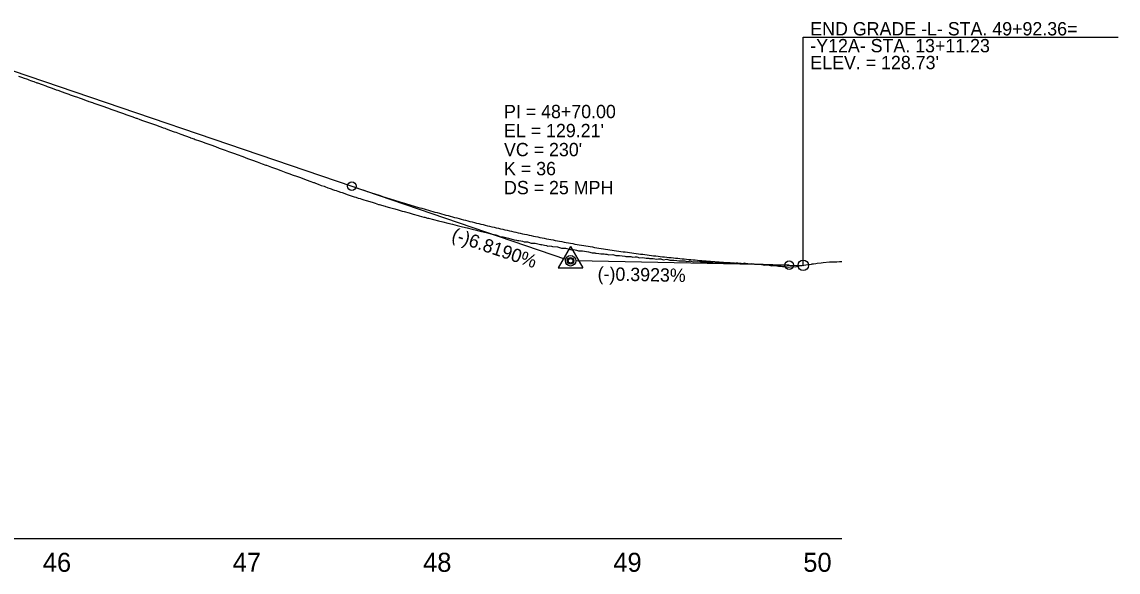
# Model space of a CAD drawing. Extents: x 1778432 to 1784301, y 601022 to 621789.
# Drawn here: x 1783724 to 1784301, y 621022 to 621311 of the extents above; entities that cross this region are included whole.
import ezdxf

# ---------------------------------------------------------------- set-up
doc = ezdxf.new("R2010")
doc.units = 0
for name, color, linetype in [('Exist Profile Cell', 7, 'Continuous'), ('Exist Vertical Profile Ground Line', 7, 'Continuous'), ('Exist Vertical Profile Horizontal Axis Label Major', 7, 'Continuous'), ('Prop PFL VPI Symbol CELL', 7, 'Continuous'), ('Prop Vertical Profile Curve Label', 7, 'Continuous'), ('Prop Vertical Profile Grade', 7, 'Continuous'), ('Prop Vertical Profile Grade Label', 7, 'Continuous'), ('Prop VPI Label', 7, 'Continuous')]:
    doc.layers.add(name, color=color, linetype=linetype)

msp = doc.modelspace()

# ---------------------------------------------------------------- linework, layer by layer
at = {"layer": 'Exist Profile Cell'}
msp.add_line((1780142.96, 621039.19), (1784155.69, 621039.19), dxfattribs=at)
at = {"layer": 'Exist Vertical Profile Ground Line'}
msp.add_lwpolyline([(1783722.62, 621282.4), (1783724.74, 621281.62), (1783725.14, 621281.48), (1783727.34, 621280.7), (1783728.1, 621280.43), (1783728.98, 621280.11), (1783729.99, 621279.74), (1783730.69, 621279.49), (1783732.29, 621278.9), (1783732.6, 621278.78), (1783735.09, 621277.91), (1783737.03, 621277.21), (1783737.73, 621276.96), (1783739.82, 621276.22), (1783741.14, 621275.75), (1783742.47, 621275.25), (1783743.28, 621274.97), (1783744.74, 621274.45), (1783745.07, 621274.34), (1783747.57, 621273.42), (1783749.05, 621272.88), (1783749.44, 621272.73), (1783749.79, 621272.61), (1783751.85, 621271.89), (1783753.59, 621271.28), (1783754.5, 621270.95), (1783755.65, 621270.54), (1783756.95, 621270.08), (1783758.29, 621269.61), (1783759.33, 621269.24), (1783759.69, 621269.12), (1783761.57, 621268.49), (1783761.92, 621268.36), (1783762.26, 621268.24), (1783764.33, 621267.5), (1783766.43, 621266.75), (1783766.97, 621266.56), (1783769.4, 621265.72), (1783771.8, 621264.82), (1783772.22, 621264.67), (1783773.91, 621264.04), (1783774.38, 621263.87), (1783774.75, 621263.75), (1783777.42, 621262.83), (1783779.61, 621262.07), (1783782.18, 621261.16), (1783784.46, 621260.34), (1783784.88, 621260.19), (1783786.48, 621259.62), (1783787.04, 621259.42), (1783787.38, 621259.3), (1783789.87, 621258.42), (1783792.08, 621257.64), (1783794.64, 621256.73), (1783796.95, 621255.89), (1783797.55, 621255.66), (1783798.66, 621255.27), (1783799.51, 621254.96), (1783799.87, 621254.84), (1783802.05, 621254.04), (1783804.55, 621253.13), (1783805.36, 621252.83), (1783807.94, 621251.88), (1783810.48, 621250.98), (1783812.85, 621250.13), (1783813.16, 621250.01), (1783815.02, 621249.32), (1783815.59, 621249.12), (1783817.84, 621248.32), (1783818.86, 621247.96), (1783821.2, 621247.09), (1783823.73, 621246.16), (1783826.27, 621245.31), (1783828.22, 621244.57), (1783828.78, 621244.35), (1783831.25, 621243.47), (1783833.15, 621242.79), (1783835.65, 621241.85), (1783838.24, 621240.94), (1783840.17, 621240.22), (1783840.63, 621240.05), (1783843.14, 621239.12), (1783845.7, 621238.18), (1783848.09, 621237.36), (1783850.76, 621236.33), (1783852.73, 621235.61), (1783853.1, 621235.47), (1783855.65, 621234.54), (1783858.28, 621233.55), (1783860.64, 621232.72), (1783863.3, 621231.73), (1783865.34, 621230.96), (1783865.67, 621230.83), (1783867.13, 621230.3), (1783867.57, 621230.13), (1783868.24, 621229.89), (1783870.89, 621228.99), (1783873.11, 621228.16), (1783875.78, 621227.2), (1783877.81, 621226.52), (1783878.14, 621226.39), (1783878.86, 621226.11), (1783880.17, 621225.58), (1783881.73, 621224.94), (1783883.33, 621224.43), (1783883.75, 621224.29), (1783885.29, 621223.69), (1783886.5, 621223.28), (1783887.08, 621223.04), (1783887.82, 621222.84), (1783888.86, 621222.47), (1783889.66, 621222.21), (1783890.64, 621221.84), (1783891.91, 621221.43), (1783892.82, 621221.11), (1783896, 621219.96), (1783899.09, 621218.93), (1783900, 621218.64), (1783901.29, 621218.25), (1783902.29, 621217.97), (1783903.11, 621217.71), (1783904.19, 621217.37), (1783905.45, 621216.96), (1783908.59, 621216.04), (1783910.21, 621215.54), (1783912.01, 621214.95), (1783912.32, 621214.86), (1783915.39, 621214), (1783915.79, 621213.87), (1783917.75, 621213.26), (1783919.81, 621212.71), (1783920.49, 621212.51), (1783922.27, 621212.06), (1783922.81, 621211.93), (1783924.46, 621211.41), (1783925.39, 621211.13), (1783928.02, 621210.4), (1783930.26, 621209.75), (1783932.87, 621209.03), (1783933.32, 621208.91), (1783935.79, 621208.28), (1783936.3, 621208.14), (1783937.77, 621207.75), (1783938.32, 621207.61), (1783940.88, 621206.91), (1783943.48, 621206.29), (1783945.8, 621205.69), (1783948.44, 621205.06), (1783950.8, 621204.47), (1783953.33, 621203.81), (1783956.18, 621203.13), (1783958.57, 621202.54), (1783961.13, 621201.91), (1783963.58, 621201.32), (1783963.99, 621201.22), (1783966.09, 621200.68), (1783968.62, 621200.08), (1783971.06, 621199.47), (1783973.58, 621198.9), (1783975.08, 621198.39), (1783976.15, 621197.92), (1783977.57, 621197.82), (1783978.21, 621197.64), (1783980.4, 621197.14), (1783981.62, 621196.83), (1783983.27, 621196.3), (1783984.55, 621196.16), (1783985.05, 621195.98), (1783985.71, 621195.96), (1783986.84, 621195.72), (1783987.7, 621195.53), (1783988.6, 621195.19), (1783989.77, 621195.22), (1783990.39, 621195.17), (1783990.86, 621195.05), (1783992.17, 621194.55), (1783994.26, 621194.47), (1783997.21, 621193.83), (1783997.52, 621193.74), (1783997.93, 621193.75), (1783999.31, 621193.52), (1784000.38, 621193.25), (1784001.09, 621192.97), (1784002.02, 621193.05), (1784002.87, 621193.03), (1784003.51, 621192.84), (1784006.12, 621192.54), (1784006.65, 621192.49), (1784008.2, 621191.95), (1784010.21, 621191.87), (1784013.01, 621191.27), (1784013.55, 621191.11), (1784014.26, 621191.12), (1784015.34, 621190.98), (1784016.16, 621190.79), (1784017.12, 621190.45), (1784018.38, 621190.55), (1784018.91, 621190.53), (1784019.31, 621190.45), (1784022.47, 621190.02), (1784024.25, 621189.5), (1784025.65, 621189.36), (1784026.03, 621189.26), (1784026.51, 621189.28), (1784027.82, 621189.13), (1784028.83, 621188.97), (1784030.58, 621188.84), (1784031.37, 621188.81), (1784031.98, 621188.69), (1784033.16, 621188.33), (1784035.16, 621188.49), (1784036.73, 621188.04), (1784038.75, 621188), (1784041.5, 621187.64), (1784042.07, 621187.5), (1784042.81, 621187.59), (1784043.84, 621187.57), (1784044.65, 621187.44), (1784045.63, 621187.15), (1784046.91, 621187.36), (1784047.41, 621187.38), (1784047.8, 621187.3), (1784049.2, 621186.86), (1784051.01, 621187.05), (1784052.76, 621186.67), (1784054.14, 621186.59), (1784054.54, 621186.5), (1784055.05, 621186.55), (1784056.32, 621186.47), (1784057.31, 621186.32), (1784058.1, 621186.09), (1784059.14, 621186.3), (1784059.89, 621186.35), (1784060.47, 621186.21), (1784061.67, 621185.81), (1784063.62, 621186.09), (1784065.24, 621185.57), (1784067.31, 621185.67), (1784068.8, 621185.4), (1784069.96, 621185.32), (1784070.58, 621185.17), (1784071.37, 621185.27), (1784072.36, 621185.25), (1784073.12, 621185.16), (1784074.14, 621184.9), (1784075.48, 621185.13), (1784075.93, 621185.17), (1784076.27, 621185.13), (1784077.71, 621184.76), (1784079.56, 621184.95), (1784081.27, 621184.66), (1784082.62, 621184.68), (1784083.05, 621184.61), (1784083.61, 621184.67), (1784084.84, 621184.61), (1784085.78, 621184.54), (1784086.62, 621184.38), (1784087.7, 621184.59), (1784088.4, 621184.63), (1784088.94, 621184.55), (1784090.18, 621184.25), (1784092.09, 621184.61), (1784093.74, 621184.22), (1784095.26, 621184.43), (1784095.86, 621184.43), (1784097.3, 621184.2), (1784098.44, 621184.17), (1784099.08, 621184.05), (1784099.91, 621184.19), (1784100.86, 621184.2), (1784101.6, 621184.09), (1784102.65, 621183.8), (1784104, 621184.09), (1784104.42, 621184.13), (1784104.75, 621184.07), (1784106.21, 621183.65), (1784108.1, 621183.89), (1784109.77, 621183.51), (1784111.09, 621183.52), (1784111.56, 621183.44), (1784112.17, 621183.46), (1784113.34, 621183.3), (1784114.26, 621183.17), (1784115.12, 621182.95), (1784116.23, 621183.05), (1784116.9, 621183.06), (1784117.42, 621182.94), (1784118.69, 621182.62), (1784120.58, 621182.75), (1784122.25, 621182.36), (1784123.74, 621182.36), (1784124.42, 621182.33), (1784125.81, 621182.19), (1784126.91, 621182.08), (1784127.58, 621181.99), (1784128.48, 621182.11), (1784130.1, 621182.18), (1784131.13, 621182.07), (1784132.56, 621182.43), (1784133.24, 621182.59), (1784134.75, 621182.78), (1784136.64, 621183.06), (1784138.3, 621183.32), (1784139.58, 621183.52), (1784140.08, 621183.59), (1784140.74, 621183.68), (1784141.86, 621183.83), (1784142.69, 621183.94), (1784144.82, 621184.2), (1784145.85, 621184.33), (1784149.06, 621184.64), (1784149.76, 621184.66), (1784152.54, 621184.7), (1784152.91, 621184.72), (1784154.31, 621184.82), (1784155.36, 621184.92), (1784155.69, 621184.95)], dxfattribs=at)
at = {"layer": 'Prop PFL VPI Symbol CELL'}
for p, q in [((1784012.95, 621192.74), (1784006.5, 621181.54)), ((1784012.95, 621192.74), (1784019.45, 621181.54)), ((1784006.5, 621181.54), (1784019.45, 621181.54))]:
    msp.add_line(p, q, dxfattribs=at)
for radius in [1.75, 1.2]:
    msp.add_circle((1784012.96, 621185.26), radius, dxfattribs=at)
at = {"layer": 'Prop Vertical Profile Curve Label'}
for centre in [(1783897.96, 621224.46), (1784127.96, 621183.01)]:
    msp.add_circle(centre, 2.25, dxfattribs=at)
at = {"layer": 'Prop Vertical Profile Grade'}
for p, q in [((1783692.96, 621294.34), (1783897.96, 621224.46)), ((1784127.96, 621183.01), (1784135.32, 621182.86))]:
    msp.add_line(p, q, dxfattribs=at)
msp.add_spline([(1783897.96, 621224.46), (1783902.56, 621222.91), (1783907.16, 621221.38), (1783911.76, 621219.89), (1783916.36, 621218.42), (1783920.96, 621216.99), (1783925.56, 621215.58), (1783930.16, 621214.21), (1783934.76, 621212.86), (1783939.36, 621211.54), (1783943.96, 621210.26), (1783948.56, 621209), (1783953.16, 621207.77), (1783957.76, 621206.57), (1783962.36, 621205.4), (1783966.96, 621204.26), (1783971.56, 621203.15), (1783976.16, 621202.07), (1783980.76, 621201.02), (1783985.36, 621200), (1783989.96, 621199.01), (1783994.56, 621198.05), (1783999.16, 621197.11), (1784003.76, 621196.21), (1784008.36, 621195.34), (1784012.96, 621194.49), (1784017.56, 621193.68), (1784022.16, 621192.9), (1784026.76, 621192.14), (1784031.36, 621191.42), (1784035.96, 621190.72), (1784040.56, 621190.05), (1784045.16, 621189.42), (1784049.76, 621188.81), (1784054.36, 621188.23), (1784058.96, 621187.68), (1784063.56, 621187.16), (1784068.16, 621186.67), (1784072.76, 621186.22), (1784077.36, 621185.79), (1784081.96, 621185.38), (1784086.56, 621185.01), (1784091.16, 621184.67), (1784095.76, 621184.36), (1784100.36, 621184.08), (1784104.96, 621183.83), (1784109.56, 621183.6), (1784114.16, 621183.41), (1784118.76, 621183.25), (1784123.36, 621183.11), (1784127.96, 621183.01)], degree=3, dxfattribs=at)
at = {"layer": 'Prop VPI Label'}
for p, q in [((1784135.32, 621182.86), (1784135.32, 621302.86)), ((1784135.32, 621302.86), (1784300.88, 621302.86)), ((1783897.96, 621224.46), (1784010.36, 621186.14)), ((1784127.96, 621183.01), (1784015.71, 621185.2))]:
    msp.add_line(p, q, dxfattribs=at)
for centre in [(1784012.96, 621185.26), (1784135.32, 621182.86)]:
    msp.add_circle(centre, 2.75, dxfattribs=at)

# ---------------------------------------------------------------- texts
at = {"layer": 'Exist Vertical Profile Horizontal Axis Label Major'}
for s, p in [('46', (1783735.44, 621021.69)), ('47', (1783835.3, 621021.69)), ('48', (1783935.43, 621021.69)), ('49', (1784035.47, 621021.69)), ('50', (1784135.35, 621021.69))]:
    msp.add_text(s, height=10, dxfattribs=at).set_placement(p)
at = {"layer": 'Prop Vertical Profile Curve Label'}
for s, p in [("VC = 230'", (1783977.96, 621240.26)), ('K = 36', (1783977.96, 621230.26)), ('DS = 25 MPH', (1783977.96, 621220.26))]:
    msp.add_text(s, height=7, dxfattribs=at).set_placement(p)
at = {"layer": 'Prop Vertical Profile Grade Label'}
for s, rotation, p in [('(-)6.8190%', 341.17617, (1783949.91, 621196.18)), ('(-)0.3923%', 358.87926, (1784027.14, 621174.98))]:
    msp.add_text(s, height=7, rotation=rotation, dxfattribs=at).set_placement(p)
at = {"layer": 'Prop VPI Label'}
for s, p in [('END GRADE -L- STA. 49+92.36=', (1784139.04, 621303.78)), ('-Y12A- STA. 13+11.23', (1784139.04, 621294.91)), ("ELEV. = 128.73'", (1784139.04, 621286.03)), ('PI = 48+70.00', (1783977.96, 621260.26)), ("EL = 129.21'", (1783977.96, 621250.26))]:
    msp.add_text(s, height=7, dxfattribs=at).set_placement(p)

doc.saveas('drawing.dxf')
